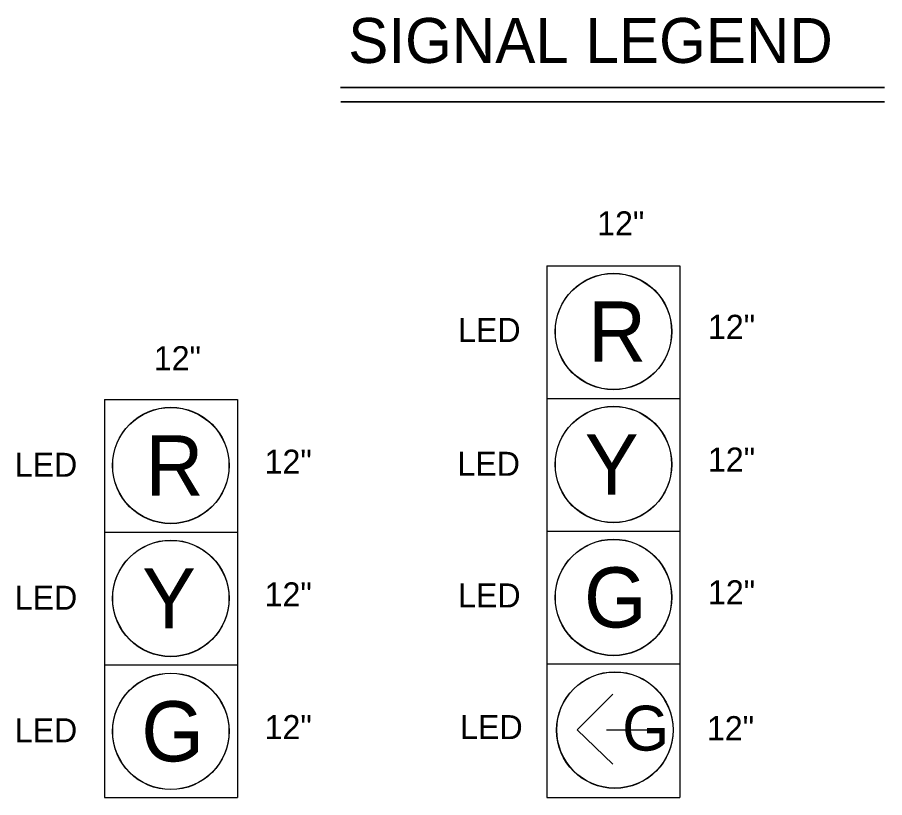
# Model space of a CAD drawing. Extents: x 488740 to 507913, y 466518 to 497949.
# Drawn here: x 507910.1954 to 507910.4675, y 496047.0364 to 496047.2814 of the extents above; entities that cross this region are included whole.
import ezdxf

# ---------------------------------------------------------------- set-up
doc = ezdxf.new("R2010")
doc.units = 0
doc.layers.add('31', color=7, linetype='Continuous')

msp = doc.modelspace()

# ---------------------------------------------------------------- linework, layer by layer
at = {"layer": '31'}
for p, q in [((507910.29678, 496047.25939), (507910.46747, 496047.25939)), ((507910.29682, 496047.25947), (507910.46751, 496047.25947)), ((507910.29686, 496047.25484), (507910.46747, 496047.25484)), ((507910.29689, 496047.25492), (507910.46751, 496047.25492)), ((507910.36155, 496047.20341), (507910.36155, 496047.07841)), ((507910.36155, 496047.20341), (507910.40322, 496047.20341)), ((507910.36155, 496047.20341), (507910.36155, 496047.07841)), ((507910.36155, 496047.20341), (507910.40322, 496047.20341)), ((507910.40322, 496047.20341), (507910.40322, 496047.12008)), ((507910.40322, 496047.20341), (507910.40322, 496047.12008)), ((507910.22277, 496047.16142), (507910.22277, 496047.03642)), ((507910.22277, 496047.16142), (507910.26444, 496047.16142)), ((507910.22277, 496047.16142), (507910.22277, 496047.03642)), ((507910.22277, 496047.16142), (507910.26444, 496047.16142)), ((507910.26444, 496047.16142), (507910.26444, 496047.07808)), ((507910.26444, 496047.16142), (507910.26444, 496047.07808)), ((507910.36155, 496047.16175), (507910.40322, 496047.16175)), ((507910.36155, 496047.16175), (507910.40322, 496047.16175)), ((507910.22277, 496047.11975), (507910.26444, 496047.11975)), ((507910.22277, 496047.11975), (507910.26444, 496047.11975)), ((507910.36155, 496047.12008), (507910.40322, 496047.12008)), ((507910.36155, 496047.12008), (507910.40322, 496047.12008)), ((507910.40322, 496047.12008), (507910.40322, 496047.12008)), ((507910.40322, 496047.12008), (507910.40322, 496047.07841)), ((507910.40322, 496047.12008), (507910.40322, 496047.12008)), ((507910.40322, 496047.12008), (507910.40322, 496047.07841)), ((507910.22277, 496047.07808), (507910.26444, 496047.07808)), ((507910.22277, 496047.07808), (507910.26444, 496047.07808)), ((507910.26444, 496047.07808), (507910.26444, 496047.07808)), ((507910.26444, 496047.07808), (507910.26444, 496047.03642)), ((507910.26444, 496047.07808), (507910.26444, 496047.07808)), ((507910.26444, 496047.07808), (507910.26444, 496047.03642)), ((507910.36155, 496047.07841), (507910.36155, 496047.03642)), ((507910.36155, 496047.07841), (507910.40322, 496047.07841)), ((507910.36155, 496047.07841), (507910.40322, 496047.07841)), ((507910.36155, 496047.07841), (507910.36155, 496047.03642)), ((507910.36155, 496047.07841), (507910.40322, 496047.07841)), ((507910.36155, 496047.07841), (507910.40322, 496047.07841)), ((507910.40322, 496047.07841), (507910.40322, 496047.03642)), ((507910.40322, 496047.07841), (507910.40322, 496047.03642)), ((507910.37106, 496047.05774), (507910.38222, 496047.0689)), ((507910.37106, 496047.05774), (507910.38222, 496047.0689)), ((507910.37106, 496047.05774), (507910.38222, 496047.04692)), ((507910.37106, 496047.05774), (507910.38222, 496047.04692)), ((507910.38025, 496047.05774), (507910.39567, 496047.05774)), ((507910.38025, 496047.05774), (507910.39567, 496047.05774)), ((507910.22277, 496047.03642), (507910.26444, 496047.03642)), ((507910.22277, 496047.03642), (507910.26444, 496047.03642)), ((507910.36155, 496047.03642), (507910.40322, 496047.03642)), ((507910.36155, 496047.03642), (507910.40322, 496047.03642))]:
    msp.add_line(p, q, dxfattribs=at)
for centre in [(507910.38241, 496047.18271), (507910.38245, 496047.18279), (507910.24352, 496047.14066), (507910.24355, 496047.14074), (507910.38241, 496047.14098), (507910.38245, 496047.14105), (507910.24352, 496047.09893), (507910.24355, 496047.09901), (507910.38241, 496047.09924), (507910.38245, 496047.09932), (507910.24352, 496047.0572), (507910.24355, 496047.05728), (507910.38284, 496047.0576), (507910.38288, 496047.05768)]:
    msp.add_circle(centre, 0.01826, dxfattribs=at)

# ---------------------------------------------------------------- texts
for s, height, p in [('SIGNAL LEGEND', 0.0141083, (507910.29921, 496047.26706)), ('SIGNAL LEGEND', 0.0141083, (507910.29921, 496047.26706)), ('12"', 0.007545, (507910.3773, 496047.21293)), ('12"', 0.007545, (507910.3773, 496047.21293)), ('R', 0.01881, (507910.37446, 496047.1733)), ('R', 0.01881, (507910.37449, 496047.17338)), ('LED', 0.007545, (507910.33366, 496047.17946)), ('12"', 0.007545, (507910.41207, 496047.18045)), ('12"', 0.007545, (507910.41207, 496047.18045)), ('12"', 0.007545, (507910.23819, 496047.1706)), ('12"', 0.007545, (507910.23819, 496047.1706)), ('Y', 0.01881, (507910.37351, 496047.13165)), ('R', 0.01881, (507910.23556, 496047.13126)), ('R', 0.01881, (507910.23559, 496047.13134)), ('Y', 0.01881, (507910.37347, 496047.13157)), ('12"', 0.007545, (507910.27297, 496047.13812)), ('12"', 0.007545, (507910.27297, 496047.13812)), ('12"', 0.007545, (507910.41207, 496047.13878)), ('12"', 0.007545, (507910.41207, 496047.13878)), ('LED', 0.007545, (507910.19455, 496047.13714)), ('LED', 0.007545, (507910.33345, 496047.13745)), ('Y', 0.01881, (507910.23457, 496047.08953)), ('Y', 0.01881, (507910.23461, 496047.08961)), ('G', 0.01881, (507910.37319, 496047.08984)), ('G', 0.01881, (507910.37323, 496047.08992)), ('12"', 0.007545, (507910.41207, 496047.09711)), ('12"', 0.007545, (507910.41207, 496047.09711)), ('LED', 0.007545, (507910.19455, 496047.09541)), ('12"', 0.007545, (507910.27297, 496047.09646)), ('12"', 0.007545, (507910.27297, 496047.09646)), ('LED', 0.007545, (507910.33366, 496047.09613)), ('G', 0.01881, (507910.23429, 496047.0478)), ('G', 0.01881, (507910.23433, 496047.04788)), ('G', 0.01411, (507910.38517, 496047.05118)), ('G', 0.01411, (507910.38517, 496047.05118)), ('LED', 0.007545, (507910.19455, 496047.05381)), ('12"', 0.007545, (507910.27297, 496047.05479)), ('12"', 0.007545, (507910.27297, 496047.05479)), ('LED', 0.007545, (507910.33432, 496047.05479)), ('12"', 0.007545, (507910.41175, 496047.05446)), ('12"', 0.007545, (507910.41175, 496047.05446))]:
    msp.add_text(s, height=height, dxfattribs=at).set_placement(p)

doc.saveas('drawing.dxf')
